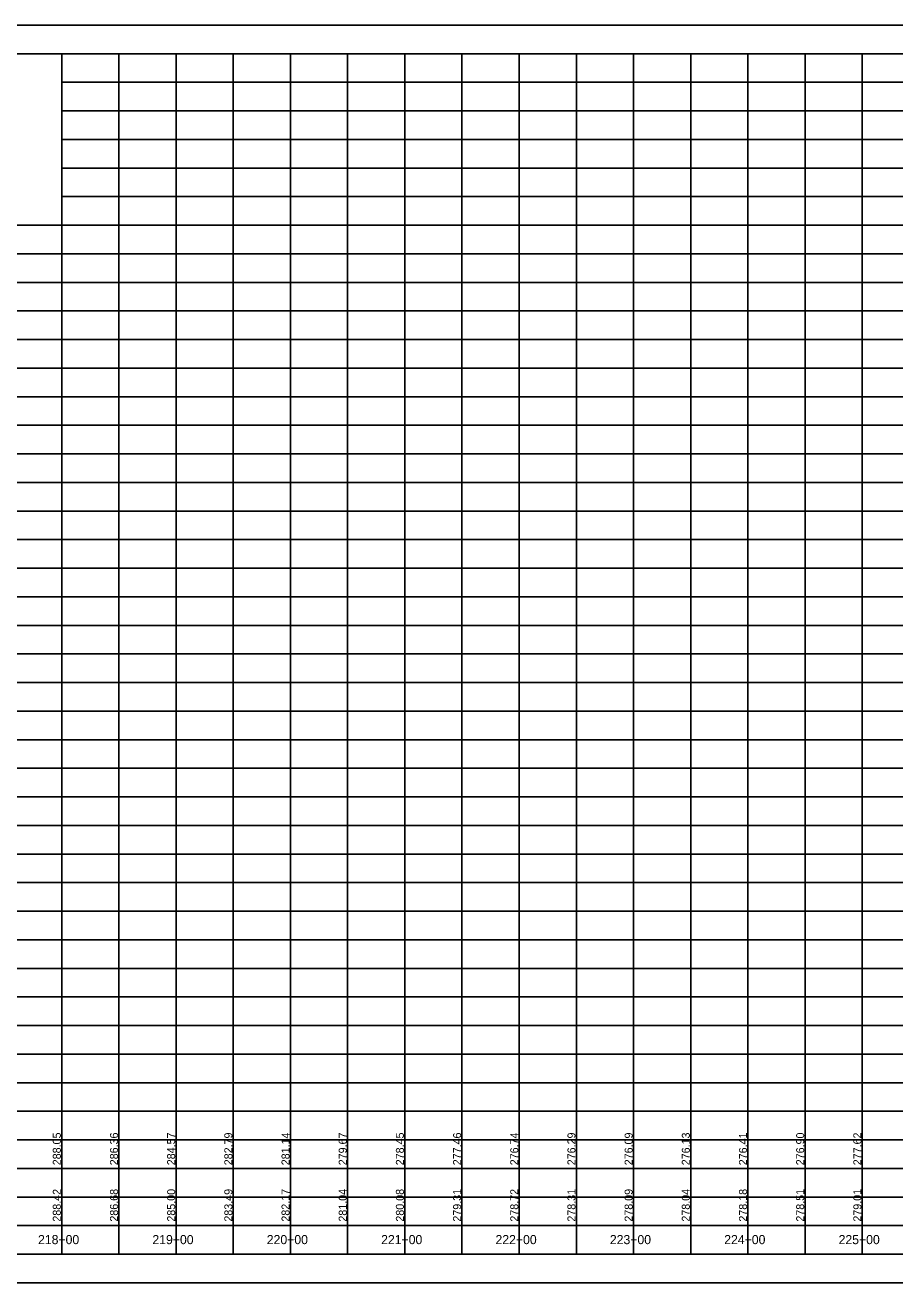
# Model space of a CAD drawing. Extents: x 1873632 to 1926512, y 813126 to 836257.
# Drawn here: x 1900131 to 1900891, y 831005 to 832105 of the extents above; entities that cross this region are included whole.
import ezdxf

# ---------------------------------------------------------------- set-up
doc = ezdxf.new("R2010")
doc.units = 0
for name, color, linetype in [('RD_DDB_StaTX', 7, 'Continuous'), ('RD_DDB_StripGrade', 7, 'Continuous'), ('RD_PD_WallFill', 7, 'Continuous'), ('RD_SHT_IplotShp', 7, 'Continuous')]:
    doc.layers.add(name, color=color, linetype=linetype)

msp = doc.modelspace()

# ---------------------------------------------------------------- linework, layer by layer
at = {"layer": 'RD_PD_WallFill'}
for p, q in [((1899712.9, 832079.6), (1905062.9, 832079.6)), ((1899712.9, 832079.6), (1901462.9, 832079.6)), ((1900162.9, 831029.6), (1900162.9, 832079.6)), ((1900162.9, 831029.6), (1900162.9, 832079.6)), ((1900212.9, 831029.6), (1900212.9, 832079.6)), ((1900212.9, 831029.6), (1900212.9, 832079.6)), ((1900262.9, 831029.6), (1900262.9, 832079.6)), ((1900262.9, 831029.6), (1900262.9, 832079.6)), ((1900312.9, 831029.6), (1900312.9, 832079.6)), ((1900312.9, 831029.6), (1900312.9, 832079.6)), ((1900362.9, 831029.6), (1900362.9, 832079.6)), ((1900362.9, 831029.6), (1900362.9, 832079.6)), ((1900412.9, 831029.6), (1900412.9, 832079.6)), ((1900412.9, 831029.6), (1900412.9, 832079.6)), ((1900462.9, 831029.6), (1900462.9, 832079.6)), ((1900462.9, 831029.6), (1900462.9, 832079.6)), ((1900512.9, 831029.6), (1900512.9, 832079.6)), ((1900512.9, 831029.6), (1900512.9, 832079.6)), ((1900562.9, 831029.6), (1900562.9, 832079.6)), ((1900562.9, 831029.6), (1900562.9, 832079.6)), ((1900612.9, 831029.6), (1900612.9, 832079.6)), ((1900612.9, 831029.6), (1900612.9, 832079.6)), ((1900662.9, 831029.6), (1900662.9, 832079.6)), ((1900662.9, 831029.6), (1900662.9, 832079.6)), ((1900712.9, 831029.6), (1900712.9, 832079.6)), ((1900712.9, 831029.6), (1900712.9, 832079.6)), ((1900762.9, 831029.6), (1900762.9, 832079.6)), ((1900762.9, 831029.6), (1900762.9, 832079.6)), ((1900812.9, 831029.6), (1900812.9, 832079.6)), ((1900812.9, 831029.6), (1900812.9, 832079.6)), ((1900862.9, 831029.6), (1900862.9, 832079.6)), ((1900862.9, 831029.6), (1900862.9, 832079.6)), ((1900162.9, 832054.6), (1905062.9, 832054.6)), ((1900162.9, 832054.6), (1905062.9, 832054.6)), ((1900162.9, 832029.6), (1905062.9, 832029.6)), ((1900162.9, 832004.6), (1905062.9, 832004.6)), ((1900162.9, 831979.6), (1905062.9, 831979.6)), ((1900162.9, 831954.6), (1905062.9, 831954.6)), ((1899712.9, 831929.6), (1905062.9, 831929.6)), ((1899712.9, 831904.6), (1905062.9, 831904.6)), ((1899712.9, 831879.6), (1905062.9, 831879.6)), ((1899712.9, 831854.6), (1905062.9, 831854.6)), ((1899712.9, 831829.6), (1905062.9, 831829.6)), ((1899712.9, 831804.6), (1905062.9, 831804.6)), ((1899712.9, 831779.6), (1905062.9, 831779.6)), ((1899712.9, 831754.6), (1905062.9, 831754.6)), ((1899712.9, 831729.6), (1905062.9, 831729.6)), ((1899712.9, 831704.6), (1905062.9, 831704.6)), ((1899712.9, 831679.6), (1905062.9, 831679.6)), ((1899712.9, 831654.6), (1905062.9, 831654.6)), ((1899712.9, 831629.6), (1905062.9, 831629.6)), ((1899712.9, 831604.6), (1905062.9, 831604.6)), ((1899712.9, 831579.6), (1905062.9, 831579.6)), ((1899712.9, 831554.6), (1905062.9, 831554.6)), ((1899712.9, 831529.6), (1905062.9, 831529.6)), ((1899712.9, 831504.6), (1905062.9, 831504.6)), ((1899712.9, 831479.6), (1905062.9, 831479.6)), ((1899712.9, 831454.6), (1905062.9, 831454.6)), ((1899712.9, 831429.6), (1905062.9, 831429.6)), ((1899712.9, 831404.6), (1905062.9, 831404.6)), ((1899712.9, 831379.6), (1905062.9, 831379.6)), ((1899712.9, 831354.6), (1905062.9, 831354.6)), ((1899712.9, 831329.6), (1905062.9, 831329.6)), ((1899712.9, 831304.6), (1905062.9, 831304.6)), ((1899712.9, 831279.6), (1905062.9, 831279.6)), ((1899712.9, 831254.6), (1905062.9, 831254.6)), ((1899712.9, 831229.6), (1905062.9, 831229.6)), ((1899712.9, 831204.6), (1905062.9, 831204.6)), ((1899712.9, 831179.6), (1905062.9, 831179.6)), ((1899712.9, 831154.6), (1905062.9, 831154.6)), ((1899712.9, 831129.6), (1905062.9, 831129.6)), ((1899712.9, 831104.6), (1905062.9, 831104.6)), ((1899712.9, 831079.6), (1905062.9, 831079.6)), ((1899712.9, 831054.6), (1905062.9, 831054.6)), ((1899712.9, 831029.6), (1905062.9, 831029.6)), ((1899712.9, 831029.6), (1905062.9, 831029.6))]:
    msp.add_line(p, q, dxfattribs=at)
msp.add_lwpolyline([(1899762.9, 832079.6), (1900162.9, 832079.6), (1900162.9, 831929.6), (1899762.9, 831929.6)], close=True, dxfattribs=at)
msp.add_lwpolyline([(1899762.9, 832079.6), (1900162.9, 832079.6), (1900162.9, 831929.6), (1899762.9, 831929.6)], close=True, dxfattribs=at)
msp.add_lwpolyline([(1899762.9, 832079.6), (1900162.9, 832079.6), (1900162.9, 831929.6), (1899762.9, 831929.6)], close=True, dxfattribs=at)
msp.add_lwpolyline([(1899762.9, 832079.6), (1900162.9, 832079.6), (1900162.9, 831929.6), (1899762.9, 831929.6)], close=True, dxfattribs=at)
at = {"layer": 'RD_SHT_IplotShp'}
msp.add_lwpolyline([(1899687.9, 831004.6), (1905087.9, 831004.6), (1905087.9, 832104.6), (1899687.9, 832104.6)], close=True, dxfattribs=at)

# ---------------------------------------------------------------- texts
at = {"layer": 'RD_DDB_StaTX'}
for s, p in [('218+00', (1900142.2, 831038.4)), ('219+00', (1900242.2, 831038.4)), ('220+00', (1900342.2, 831038.4)), ('221+00', (1900442.2, 831038.4)), ('222+00', (1900542.2, 831038.4)), ('223+00', (1900642.2, 831038.4)), ('224+00', (1900742.2, 831038.4)), ('225+00', (1900842.2, 831038.4))]:
    msp.add_text(s, height=8, dxfattribs=at).set_placement(p)
at = {"layer": 'RD_DDB_StripGrade'}
for s, p in [('288.05', (1900162.1, 831107.4)), ('286.36', (1900212.1, 831107.4)), ('284.57', (1900262.1, 831107.4)), ('282.79', (1900312.1, 831107.4)), ('281.14', (1900362.1, 831107.4)), ('279.67', (1900412.1, 831107.4)), ('278.45', (1900462.1, 831107.4)), ('277.46', (1900512.1, 831107.4)), ('276.74', (1900562.1, 831107.4)), ('276.29', (1900612.1, 831107.4)), ('276.09', (1900662.1, 831107.4)), ('276.13', (1900712.1, 831107.4)), ('276.41', (1900762.1, 831107.4)), ('276.90', (1900812.1, 831107.4)), ('277.62', (1900862.1, 831107.4)), ('288.42', (1900162.1, 831058.1)), ('286.68', (1900212.1, 831058.1)), ('285.00', (1900262.1, 831058.1)), ('283.49', (1900312.1, 831058.1)), ('282.17', (1900362.1, 831058.1)), ('281.04', (1900412.1, 831058.1)), ('280.08', (1900462.1, 831058.1)), ('279.31', (1900512.1, 831058.1)), ('278.72', (1900562.1, 831058.1)), ('278.31', (1900612.1, 831058.1)), ('278.09', (1900662.1, 831058.1)), ('278.04', (1900712.1, 831058.1)), ('278.18', (1900762.1, 831058.1)), ('278.51', (1900812.1, 831058.1)), ('279.01', (1900862.1, 831058.1))]:
    msp.add_text(s, height=7, rotation=90, dxfattribs=at).set_placement(p)

doc.saveas('drawing.dxf')
